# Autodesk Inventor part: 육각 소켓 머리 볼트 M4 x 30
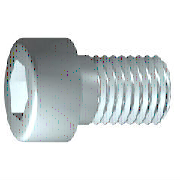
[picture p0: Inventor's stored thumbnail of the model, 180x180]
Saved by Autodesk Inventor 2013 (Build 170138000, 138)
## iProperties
IsCustomPart: 1
Created: 2012-02
Part Number: 육각 소켓 머리 볼트 M4 x 30
Material: 강철, 연강
Description: 원통형 머리 캡 나사
Document SubType Name: Modeling
Standard: JIS B 1176
Designer: mdu-01
Standards Organization: JIS
Language: ko-KR
Size Designation: M4 x 30
Categories: <MemberInstance><Categories><Category DisplayName="조임쇠" InternalName="e4da775c-781d-43d5-af7c-5136215cf5a6" Mnemonic="FSTN"><Category DisplayName="볼트" InternalN
Density: 1 g/cm^3
Author: mdu-01
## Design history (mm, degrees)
sketch "스케치1"
  geometry: L1 (-1, 0)-(30, 0); L2 (30, 0)-(30, 2); L3 (30, 2)-(10, 2); L4 (10, 2)-(9.57, 2); L5 (9.57, 2)-(0, 2); L6 (0, 2)-(0, 3.5); L7 (0, 3.5)-(-4, 3.5); L8 (-4, 3.5)-(-4, 1.732); L9 (-4, 1.732)-(-2, 1.732); L10 (-2, 1.732)-(-1, 0); L11 (-10.8, 0)-(36.8, 0) reference; L12 (0, -0.7)-(0, 4.2) reference; L13 (10, 2)-(0, 2)
  constraints: 22 end point, 6 parallel, 2 collinear, 2 perpendicular, 1 horizontal, 1 point on line
  dimensions: "d1" = 20 distance from line of L3.end L2 (= GEL); "d2" = 0.42952 distance of L4.end L3.end (computed from GAL); "d3" = 4 distance between parallel lines of L8 L6 (= KOH); "d4" = 2 distance of L8.end L9.end (= INTI); "d5" = 60 deg angle of L10 L1; "d6" = 4 diameter of L3 L1 (= GD); "d7" = 4 diameter of L5 L1 (= BDM); "d8" = 3.4641 diameter of L9 L1 (= 1.1547 x SW); "d9" = 7 diameter of L7 L1 (= KOD); "d26" = 30 distance between parallel lines of L12 L2 (= NLG)
revolve "본체" sketch "스케치1" stored, may be unused: angle "d10" = 90 deg
sketch "스케치2"
  geometry: L1 (0, -4.9)-(0, 4.9) reference; L2 (-4.9, 0)-(4.9, 0) reference; L3 (1.732, 0)-(0.866, -1.5); L4 (0.866, -1.5)-(-0.866, -1.5); L5 (-0.866, -1.5)-(-1.732, 0); L6 (-1.732, 0)-(-0.866, 1.5); L7 (-0.866, 1.5)-(0.866, 1.5); L8 (0.866, 1.5)-(1.732, 0); 2 further points
  constraints: 12 end point, 1 coincident, 1 horizontal alignment, 1 point on line, 12 other
extrude "슬롯" join sketch "스케치2" stored distance "d11" = 10; taper "d12" = 0 deg
workplane "Work Plane1"
fillet "Fillet2" dims "d30" = 0.1 (= R)
body "Solid1"
fillet "모깎기1" dims "d17" = 0.4 (= RR)
feature "스레드" dims "d13" = 20 (= GEL), "d14" = 0
chamfer "모따기1" distance "d15" = 0.42941 (= -0.5 x SPD + 0.5 x GD); stored, may be unused: second distance "d16" = 0.42941 (= GUL), angle "d27" = 45 deg
other parameters: "GD" = 4 (= NND) [user parameter; used in 2 equation terms], "NLG" = 30 [user parameter; used in 1 equation term], "GEL" = 20 [user parameter; used in 2 equation terms], "KOD" = 7 [user parameter; used in 1 equation term], "KOH" = 4 [user parameter; used in 1 equation term], "INTI" = 2 [user parameter; used in 1 equation term], "GAL" = 0.42941 (= 0.61345 x PTC) [user parameter; used in 1 equation term], "GUL" = 0.42941 (= 0.61345 x PTC) [user parameter; used in 1 equation term], "BDM" = 4 (= NND) [user parameter; used in 1 equation term], "SW" = 3 [user parameter; used in 2 equation terms], "RR" = 0.4 [user parameter; used in 1 equation term], "SPD" = 3.14117 (= NND - 1.2269 x PTC) [user parameter; used in 1 equation term], "d19" = 0, "d28" = 0, "d29" = 0, "R" = 0.1 [user parameter; used in 1 equation term], "PHH" = 0.2 [user parameter], "GD1" = 3.14117 (= THREADDIA - 1.2269 x PTC) [user parameter], "THREADDIA" = 4 [user parameter; used in 1 equation term], "FAWI" = 45 deg [user parameter], "TPU" = 14.28571 (computed from PTC) [user parameter], "PTC" = 0.7 [user parameter; used in 5 equation terms], "NND" = 4 [user parameter; used in 3 equation terms], "TOA" = 30 deg [user parameter], "E0" = 3.465 (= 1.155 x SW) [user parameter]
